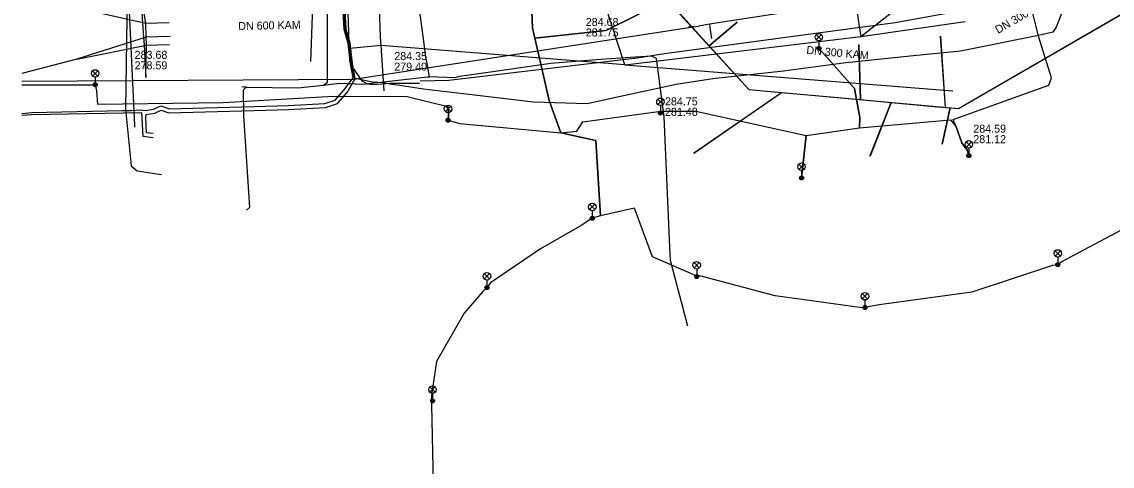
# Model space of a CAD drawing. Extents: x -599854 to -599675, y -1160809 to -1160543.
# Drawn here: x -599854.4 to -599745.4, y -1160665.1 to -1160620.8 of the extents above; entities that cross this region are included whole.
import ezdxf

# ---------------------------------------------------------------- set-up
doc = ezdxf.new("R2010")
doc.units = 0
for name, color, linetype in [('BKOM-ODVODNENI_trasa sítě', 7, 'Continuous'), ('BVK-JEDNOTNA_popisy', 7, 'Continuous'), ('BVK-VODOVOD_trasa sítě', 7, 'Continuous'), ('BVK-VODOVOD_trasa zrušené sítě', 7, 'Continuous'), ('CETIN_kabel podzemní', 7, 'Continuous'), ('DESTOVA-NEPROVOZOVANA_popisy', 7, 'Continuous'), ('DESTOVA_trasa neprovozované sítě', 7, 'Continuous'), ('DPMB_trolejové vedení-nosné lano', 7, 'Continuous'), ('DSP-JEDNOTNA-BVK_trasa sítě', 7, 'Continuous'), ('EON-NN_kabel', 7, 'Continuous'), ('EON-VN_kabel', 7, 'Continuous'), ('EON-VN_kabel zrušené sítě', 7, 'Continuous'), ('INNOGY-STL_trasa sítě', 7, 'Continuous'), ('TSB_kabel VO', 7, 'Continuous'), ('TSB_lampy VO', 7, 'Continuous')]:
    doc.layers.add(name, color=color, linetype=linetype)

msp = doc.modelspace()

# ---------------------------------------------------------------- linework, layer by layer
at = {"layer": 'BKOM-ODVODNENI_trasa sítě'}
for points in [[(-599760.76, -1160629.44), (-599734.15, -1160614)], [(-599790.33, -1160618.08), (-599781.73, -1160627.53)], [(-599782.89, -1160620.82), (-599785.679, -1160623.191)], [(-599762.55, -1160622.224), (-599762.081, -1160629.32)], [(-599770.714, -1160623.06), (-599770.546, -1160628.549)], [(-599787.215, -1160633.879), (-599778.44, -1160627.83)], [(-599781.73, -1160627.53), (-599760.76, -1160629.44)], [(-599769.597, -1160634.144), (-599767.509, -1160628.825)], [(-599762.401, -1160632.981), (-599761.583, -1160629.365)]]:
    msp.add_lwpolyline(points, dxfattribs=at)
at = {"layer": 'BVK-JEDNOTNA_popisy'}
for p, q in [((-599843.102, -1160624.605), (-599843.102, -1160624.605)), ((-599817.149, -1160624.73), (-599817.149, -1160624.73))]:
    msp.add_line(p, q, dxfattribs=at)
at = {"layer": 'BVK-VODOVOD_trasa sítě'}
msp.add_lwpolyline([(-599843.85, -1160617.9), (-599843.85, -1160618.1), (-599844.02, -1160629.49), (-599843.44, -1160635.17), (-599842.84, -1160635.66), (-599840.428, -1160636.038)], dxfattribs=at)
at = {"layer": 'BVK-VODOVOD_trasa zrušené sítě'}
for p, q in [((-599787.48, -1160621.25), (-599787.169, -1160621.208)), ((-599785.657, -1160621.012), (-599786.76, -1160621.23)), ((-599785.657, -1160621.012), (-599785.6, -1160621.34)), ((-599785.6, -1160621.34), (-599785.44, -1160622.44))]:
    msp.add_line(p, q, dxfattribs=at)
for points in [[(-599679.2237, -1160599.5579), (-599732.933, -1160612.912), (-599785.657, -1160621.012)], [(-599854.3744, -1160626.7017), (-599821.206, -1160626.503), (-599787.72, -1160621.365), (-599786.76, -1160621.23)], [(-599787.72, -1160621.365), (-599787.732, -1160621.288), (-599787.48, -1160621.25)]]:
    msp.add_lwpolyline(points, dxfattribs=at)
at = {"layer": 'CETIN_kabel podzemní'}
for points in [[(-599824.21, -1160627.1), (-599823.81, -1160626.82), (-599823.81, -1160615.51), (-599823.3, -1160614.12)], [(-599813.64, -1160626.29), (-599814.01, -1160624.26), (-599815.06, -1160616.21), (-599815.12, -1160614.04)], [(-599793.07, -1160624.32), (-599796.96, -1160624.59), (-599801.51, -1160624.95), (-599808.7, -1160625.98), (-599810.63, -1160626.23)], [(-599790.72, -1160626.2), (-599790.96, -1160624.46), (-599791.4, -1160624.2), (-599793.07, -1160624.32)], [(-599824.21, -1160627.1), (-599822.63, -1160626.91), (-599820.3, -1160627.01), (-599813.83, -1160626.28), (-599813.64, -1160626.29)], [(-599810.63, -1160626.23), (-599811.1, -1160626.39), (-599813.64, -1160626.29)], [(-599789.62, -1160643.27), (-599790.17, -1160630.26), (-599790.72, -1160626.2)], [(-599831.92, -1160627.32), (-599832.37, -1160627.29)], [(-599831.92, -1160627.32), (-599832.1, -1160627.43), (-599832.24, -1160627.61), (-599832.21, -1160630.13), (-599831.61, -1160639.31), (-599831.92, -1160639.58)], [(-599831.92, -1160627.32), (-599826.8, -1160627.36), (-599824.21, -1160627.1)], [(-599787.81, -1160651.17), (-599789.56, -1160644.6), (-599789.62, -1160643.27)]]:
    msp.add_lwpolyline(points, dxfattribs=at)
at = {"layer": 'DESTOVA-NEPROVOZOVANA_popisy'}
for p, q in [((-599798.016, -1160622.246), (-599798.016, -1160622.246)), ((-599790.097, -1160630.172), (-599790.097, -1160630.172)), ((-599759.285, -1160632.897), (-599759.285, -1160632.897))]:
    msp.add_line(p, q, dxfattribs=at)
at = {"layer": 'DESTOVA_trasa neprovozované sítě'}
for p, q in [((-599825.49, -1160624.76), (-599825.3, -1160619.266)), ((-599782.89, -1160620.82), (-599785.679, -1160623.191)), ((-599762.6, -1160622.21), (-599762.081, -1160629.32)), ((-599770.74, -1160623.07), (-599770.546, -1160628.549)), ((-599787.26, -1160633.89), (-599778.444, -1160627.829)), ((-599769.6, -1160634.18), (-599767.509, -1160628.825)), ((-599762.4, -1160633), (-599761.583, -1160629.365))]:
    msp.add_line(p, q, dxfattribs=at)
for points in [[(-599760.76, -1160629.44), (-599739.456, -1160617.079), (-599737.061, -1160615.689), (-599734.15, -1160614)], [(-599790.33, -1160618.08), (-599789.314, -1160619.197), (-599785.679, -1160623.191), (-599781.73, -1160627.53)], [(-599781.73, -1160627.53), (-599778.444, -1160627.829), (-599770.546, -1160628.549), (-599767.509, -1160628.825), (-599762.081, -1160629.32), (-599761.583, -1160629.365), (-599760.76, -1160629.44)]]:
    msp.add_lwpolyline(points, dxfattribs=at)
at = {"layer": 'DPMB_trolejové vedení-nosné lano'}
for points in [[(-599771.54, -1160615.69), (-599770.53, -1160622.26)], [(-599770.53, -1160622.26), (-599762.45, -1160615.93)], [(-599841.968, -1160626.344), (-599841.918, -1160623.101), (-599841.952, -1160622.311), (-599841.994, -1160620.91), (-599842.088, -1160620.363), (-599842.528, -1160616.745)], [(-599842.528, -1160616.745), (-599842.355, -1160620.405), (-599842.326, -1160620.901), (-599842.2, -1160622.364), (-599842.157, -1160623.068), (-599841.968, -1160626.344)], [(-599849.894, -1160619.17), (-599841.994, -1160620.91), (-599839.648, -1160620.839)], [(-599818.53, -1160622.33), (-599818.64, -1160619.44)], [(-599794.1, -1160625.09), (-599796.09, -1160619.09)], [(-599770.53, -1160622.26), (-599760.09, -1160620.75)], [(-599839.532, -1160622.265), (-599841.952, -1160622.311), (-599848.86, -1160624.505), (-599854.3744, -1160625.9564)], [(-599818.47, -1160623.14), (-599818.53, -1160622.33)], [(-599794.1, -1160625.09), (-599770.53, -1160622.26)], [(-599848.86, -1160624.505), (-599841.918, -1160623.101), (-599839.611, -1160623.045)], [(-599818.47, -1160623.14), (-599821.582, -1160623.44)], [(-599818.472, -1160623.141), (-599818.47, -1160623.14)], [(-599794.1, -1160625.09), (-599818.472, -1160623.141)], [(-599818.15, -1160627.66), (-599818.47, -1160623.14)], [(-599794.1, -1160625.09), (-599761.33, -1160627.66)]]:
    msp.add_lwpolyline(points, dxfattribs=at)
at = {"layer": 'DSP-JEDNOTNA-BVK_trasa sítě'}
for p, q in [((-599760.76, -1160629.44), (-599739.456, -1160617.079)), ((-599789.314, -1160619.197), (-599785.679, -1160623.191)), ((-599785.679, -1160623.191), (-599782.89, -1160620.82)), ((-599762.6, -1160622.21), (-599762.081, -1160629.32)), ((-599785.679, -1160623.191), (-599781.73, -1160627.53)), ((-599770.546, -1160628.549), (-599770.74, -1160623.07)), ((-599787.26, -1160633.89), (-599778.444, -1160627.829)), ((-599781.73, -1160627.53), (-599778.444, -1160627.829)), ((-599778.444, -1160627.829), (-599770.546, -1160628.549)), ((-599770.546, -1160628.549), (-599767.509, -1160628.825)), ((-599767.509, -1160628.825), (-599769.6, -1160634.18)), ((-599767.509, -1160628.825), (-599762.081, -1160629.32)), ((-599761.583, -1160629.365), (-599762.4, -1160633)), ((-599762.081, -1160629.32), (-599761.583, -1160629.365)), ((-599761.583, -1160629.365), (-599760.76, -1160629.44))]:
    msp.add_line(p, q, dxfattribs=at)
at = {"layer": 'EON-NN_kabel'}
for points in [[(-599844.347, -1160629.647), (-599843.403, -1160629.644), (-599842.517, -1160629.564), (-599842.022, -1160629.649), (-599841.199, -1160629.508), (-599840.468, -1160629.174), (-599839.62, -1160629.458), (-599836.082, -1160629.367), (-599831.164, -1160629.231), (-599827.751, -1160629.149), (-599824.103, -1160628.941), (-599823.051, -1160628.59), (-599822.19, -1160627.612), (-599821.256, -1160626.388), (-599821.529, -1160624.975), (-599821.758, -1160622.96), (-599822.159, -1160621.557), (-599822.4, -1160617.205)], [(-599841.262, -1160631.935), (-599841.918, -1160631.867), (-599841.979, -1160630.337), (-599841.955, -1160630.044), (-599841.082, -1160629.894), (-599840.447, -1160629.604), (-599839.683, -1160629.86), (-599836.059, -1160629.767), (-599831.139, -1160629.631), (-599827.719, -1160629.548), (-599824.028, -1160629.338), (-599822.822, -1160628.936), (-599821.85, -1160627.831), (-599821.044, -1160626.432), (-599821.331, -1160624.945), (-599821.562, -1160622.92), (-599821.961, -1160621.523), (-599822.2, -1160617.195)], [(-599854.3744, -1160629.9274), (-599853.387, -1160629.841), (-599844.347, -1160629.647)], [(-599854.3744, -1160630.0994), (-599853.359, -1160630.024), (-599842.397, -1160629.838), (-599842.295, -1160632.21), (-599841.252, -1160632.339)]]:
    msp.add_lwpolyline(points, dxfattribs=at)
at = {"layer": 'EON-VN_kabel'}
for points in [[(-599817.41, -1160627.04), (-599817.969, -1160626.93), (-599818.17, -1160626.89), (-599819.337, -1160626.809), (-599820.462, -1160626.561), (-599821.15, -1160626.41), (-599821.377, -1160625.236), (-599821.43, -1160624.96), (-599821.66, -1160622.94), (-599821.681, -1160622.866), (-599822.06, -1160621.54), (-599822.3, -1160617.2)], [(-599743.23, -1160617.28), (-599748.93, -1160618.14), (-599749.59, -1160618.4), (-599750.25, -1160619.35), (-599750.99, -1160621.33), (-599751.35, -1160621.82), (-599752.03, -1160621.98), (-599752.78, -1160622.16), (-599760.56, -1160623.7), (-599765.25, -1160624.19), (-599772.02, -1160624.87), (-599778.24, -1160625.7), (-599785.33, -1160626.46), (-599788.97, -1160627.03), (-599794.53, -1160628.24), (-599797.86, -1160628.96), (-599803.25, -1160628.81), (-599809.12, -1160628.1), (-599814.22, -1160627.49), (-599816.61, -1160627.15), (-599817.41, -1160627.04)]]:
    msp.add_lwpolyline(points, dxfattribs=at)
at = {"layer": 'EON-VN_kabel zrušené sítě'}
for points in [[(-599771.83, -1160621.47), (-599767.08, -1160620.85), (-599761.41, -1160619.81), (-599756.57, -1160618.89), (-599746.77, -1160617.22), (-599743.21, -1160616.58), (-599737.23, -1160615.44), (-599733.76, -1160614.74), (-599727.53, -1160613.39), (-599722.82, -1160612.38), (-599722.81, -1160612.35), (-599713.101, -1160609.819)], [(-599821.89, -1160616.75), (-599821.681, -1160622.866), (-599821.62, -1160624.66), (-599821.45, -1160625.13), (-599821.377, -1160625.236), (-599820.462, -1160626.561), (-599820.38, -1160626.68), (-599819.82, -1160626.98), (-599819.3, -1160627.05), (-599817.969, -1160626.93), (-599817.64, -1160626.9), (-599814.64, -1160626.92)], [(-599814.557, -1160626.669), (-599811.696, -1160626.619), (-599792.86, -1160624.37), (-599790.16, -1160623.96), (-599771.83, -1160621.47)]]:
    msp.add_lwpolyline(points, dxfattribs=at)
at = {"layer": 'INNOGY-STL_trasa sítě'}
msp.add_lwpolyline([(-599843.87, -1160614.73), (-599843.799, -1160616.23), (-599843.1, -1160631.11), (-599843.1, -1160631.3)], dxfattribs=at)
at = {"layer": 'TSB_kabel VO'}
for points in [[(-599800.51, -1160631.88), (-599801.66, -1160628.63), (-599803.35, -1160621.4), (-599803.6, -1160615.14), (-599817.16, -1160614.58), (-599825.47, -1160614.78), (-599827.84, -1160614.21), (-599835.21, -1160614.5), (-599849.27, -1160614.99), (-599854.3744, -1160615.0219)], [(-599803.6, -1160615.14), (-599803.35, -1160621.4), (-599803.12, -1160622.43), (-599796.01, -1160621.65), (-599790.01, -1160618.69)], [(-599790.01, -1160618.69), (-599796.01, -1160621.65), (-599803.12, -1160622.43), (-599801.66, -1160628.63), (-599800.51, -1160631.88)], [(-599800.51, -1160631.88), (-599798.91, -1160631.7), (-599798.3, -1160630.78), (-599790.741, -1160629.747), (-599790.55, -1160629.89), (-599790.384, -1160629.713), (-599787.03, -1160629.69), (-599776, -1160632.13), (-599776.45, -1160636.37), (-599776, -1160632.13), (-599770.65, -1160631.36), (-599770.62, -1160630.34), (-599771.15, -1160627.45), (-599774, -1160624.23), (-599774.72, -1160623.44), (-599774, -1160624.23), (-599771.15, -1160627.45), (-599770.62, -1160630.34), (-599770.65, -1160631.36), (-599761.55, -1160630.57), (-599761, -1160631.27), (-599760.44, -1160632.88), (-599759.91, -1160633.6), (-599759.73, -1160634.14), (-599759.91, -1160633.6), (-599760.44, -1160632.88), (-599761, -1160631.27), (-599761.31, -1160630.537), (-599751.73, -1160627.11), (-599751.48, -1160626.36), (-599752.78, -1160622.23), (-599753.62, -1160618.73)], [(-599854.3744, -1160627.079), (-599847.04, -1160627.06)], [(-599847.04, -1160627.06), (-599846.91, -1160627.67), (-599846.82, -1160629.01), (-599834.24, -1160628.85), (-599823.21, -1160628.2), (-599815.85, -1160628.24), (-599811.79, -1160629.23), (-599811.72, -1160630.1), (-599811.78, -1160630.6), (-599810.61, -1160630.92), (-599800.51, -1160631.88)], [(-599800.51, -1160631.88), (-599797.02, -1160632.62), (-599796.54, -1160640.16), (-599797.36, -1160640.39), (-599798.39, -1160641.07), (-599802.54, -1160643.45), (-599807.52, -1160646.85), (-599807.89, -1160647.31), (-599808.32, -1160647.73), (-599810.17, -1160649.85), (-599812.92, -1160654.69), (-599813.41, -1160657.83), (-599813.45, -1160658.54), (-599813.42, -1160659.01), (-599813.171, -1160671.571)], [(-599742.3, -1160640.42), (-599750.4, -1160644.71), (-599750.84, -1160645.03), (-599751.36, -1160645.11), (-599759.42, -1160647.76), (-599768.7, -1160649.02), (-599770.11, -1160649.3), (-599770.4, -1160649.33), (-599779.07, -1160648.14), (-599786.62, -1160646.13), (-599786.93, -1160646.21), (-599787.22, -1160646.03), (-599791.35, -1160644.25), (-599793.13, -1160639.37), (-599796.54, -1160640.16), (-599797.02, -1160632.62), (-599800.51, -1160631.88)]]:
    msp.add_lwpolyline(points, dxfattribs=at)
at = {"layer": 'TSB_lampy VO'}
for p, q in [((-599774.985, -1160622.58), (-599774.455, -1160622.05)), ((-599774.985, -1160622.05), (-599774.455, -1160622.58)), ((-599774.985, -1160622.58), (-599774.455, -1160622.05)), ((-599774.985, -1160622.05), (-599774.455, -1160622.58)), ((-599774.72, -1160622.69), (-599774.72, -1160623.44)), ((-599774.72, -1160622.69), (-599774.72, -1160623.44)), ((-599847.305, -1160626.2), (-599846.775, -1160625.67)), ((-599847.305, -1160625.67), (-599846.775, -1160626.2)), ((-599847.305, -1160626.2), (-599846.775, -1160625.67)), ((-599847.305, -1160625.67), (-599846.775, -1160626.2)), ((-599847.04, -1160626.31), (-599847.04, -1160627.06)), ((-599847.04, -1160626.31), (-599847.04, -1160627.06)), ((-599812.045, -1160629.74), (-599811.515, -1160629.21)), ((-599812.045, -1160629.21), (-599811.515, -1160629.74)), ((-599812.045, -1160629.74), (-599811.515, -1160629.21)), ((-599812.045, -1160629.21), (-599811.515, -1160629.74)), ((-599790.815, -1160629.03), (-599790.285, -1160628.5)), ((-599790.815, -1160628.5), (-599790.285, -1160629.03)), ((-599790.815, -1160629.03), (-599790.285, -1160628.5)), ((-599790.815, -1160628.5), (-599790.285, -1160629.03)), ((-599790.55, -1160629.14), (-599790.55, -1160629.89)), ((-599790.55, -1160629.14), (-599790.55, -1160629.89)), ((-599811.78, -1160629.85), (-599811.78, -1160630.6)), ((-599811.78, -1160629.85), (-599811.78, -1160630.6)), ((-599759.995, -1160633.28), (-599759.465, -1160632.75)), ((-599759.995, -1160632.75), (-599759.465, -1160633.28)), ((-599759.995, -1160633.28), (-599759.465, -1160632.75)), ((-599759.995, -1160632.75), (-599759.465, -1160633.28)), ((-599759.73, -1160633.39), (-599759.73, -1160634.14)), ((-599759.73, -1160633.39), (-599759.73, -1160634.14)), ((-599776.715, -1160635.51), (-599776.185, -1160634.98)), ((-599776.715, -1160634.98), (-599776.185, -1160635.51)), ((-599776.715, -1160635.51), (-599776.185, -1160634.98)), ((-599776.715, -1160634.98), (-599776.185, -1160635.51)), ((-599776.45, -1160635.62), (-599776.45, -1160636.37)), ((-599776.45, -1160635.62), (-599776.45, -1160636.37)), ((-599797.625, -1160639.53), (-599797.095, -1160639)), ((-599797.625, -1160639), (-599797.095, -1160639.53)), ((-599797.625, -1160639.53), (-599797.095, -1160639)), ((-599797.625, -1160639), (-599797.095, -1160639.53)), ((-599797.36, -1160639.64), (-599797.36, -1160640.39)), ((-599797.36, -1160639.64), (-599797.36, -1160640.39)), ((-599751.105, -1160644.17), (-599750.575, -1160643.64)), ((-599751.105, -1160643.64), (-599750.575, -1160644.17)), ((-599751.105, -1160644.17), (-599750.575, -1160643.64)), ((-599751.105, -1160643.64), (-599750.575, -1160644.17)), ((-599750.84, -1160644.28), (-599750.84, -1160645.03)), ((-599750.84, -1160644.28), (-599750.84, -1160645.03)), ((-599787.195, -1160645.35), (-599786.665, -1160644.82)), ((-599787.195, -1160644.82), (-599786.665, -1160645.35)), ((-599787.195, -1160645.35), (-599786.665, -1160644.82)), ((-599787.195, -1160644.82), (-599786.665, -1160645.35)), ((-599786.93, -1160645.46), (-599786.93, -1160646.21)), ((-599786.93, -1160645.46), (-599786.93, -1160646.21)), ((-599808.155, -1160646.45), (-599807.625, -1160645.92)), ((-599808.155, -1160645.92), (-599807.625, -1160646.45)), ((-599808.155, -1160646.45), (-599807.625, -1160645.92)), ((-599808.155, -1160645.92), (-599807.625, -1160646.45)), ((-599807.89, -1160646.56), (-599807.89, -1160647.31)), ((-599807.89, -1160646.56), (-599807.89, -1160647.31)), ((-599770.375, -1160648.44), (-599769.845, -1160647.91)), ((-599770.375, -1160647.91), (-599769.845, -1160648.44)), ((-599770.375, -1160648.44), (-599769.845, -1160647.91)), ((-599770.375, -1160647.91), (-599769.845, -1160648.44)), ((-599770.11, -1160648.55), (-599770.11, -1160649.3)), ((-599770.11, -1160648.55), (-599770.11, -1160649.3)), ((-599813.594, -1160657.76), (-599813.064, -1160657.23)), ((-599813.594, -1160657.23), (-599813.064, -1160657.76)), ((-599813.594, -1160657.76), (-599813.064, -1160657.23)), ((-599813.594, -1160657.23), (-599813.064, -1160657.76)), ((-599813.329, -1160657.87), (-599813.329, -1160658.62)), ((-599813.329, -1160657.87), (-599813.329, -1160658.62))]:
    msp.add_line(p, q, dxfattribs=at)
for centre, radius in [((-599774.72, -1160622.315), 0.375), ((-599774.72, -1160622.315), 0.375), ((-599774.72, -1160623.44), 0.2), ((-599774.72, -1160623.44), 0.2), ((-599774.72, -1160623.44), 0.1445), ((-599774.72, -1160623.44), 0.1445), ((-599774.72, -1160623.44), 0.0876), ((-599774.72, -1160623.44), 0.0876), ((-599847.04, -1160625.935), 0.375), ((-599847.04, -1160625.935), 0.375), ((-599847.04, -1160627.06), 0.2), ((-599847.04, -1160627.06), 0.2), ((-599847.04, -1160627.06), 0.1445), ((-599847.04, -1160627.06), 0.1445), ((-599847.04, -1160627.06), 0.0876), ((-599847.04, -1160627.06), 0.0876), ((-599790.55, -1160628.765), 0.375), ((-599790.55, -1160628.765), 0.375), ((-599811.78, -1160629.475), 0.375), ((-599811.78, -1160629.475), 0.375), ((-599811.78, -1160630.6), 0.2), ((-599811.78, -1160630.6), 0.2), ((-599811.78, -1160630.6), 0.1445), ((-599811.78, -1160630.6), 0.1445), ((-599811.78, -1160630.6), 0.0876), ((-599811.78, -1160630.6), 0.0876), ((-599790.55, -1160629.89), 0.2), ((-599790.55, -1160629.89), 0.2), ((-599790.55, -1160629.89), 0.1445), ((-599790.55, -1160629.89), 0.1445), ((-599790.55, -1160629.89), 0.0876), ((-599790.55, -1160629.89), 0.0876), ((-599759.73, -1160633.015), 0.375), ((-599759.73, -1160633.015), 0.375), ((-599776.45, -1160635.245), 0.375), ((-599776.45, -1160635.245), 0.375), ((-599759.73, -1160634.14), 0.2), ((-599759.73, -1160634.14), 0.2), ((-599759.73, -1160634.14), 0.1445), ((-599759.73, -1160634.14), 0.1445), ((-599759.73, -1160634.14), 0.0876), ((-599759.73, -1160634.14), 0.0876), ((-599776.45, -1160636.37), 0.2), ((-599776.45, -1160636.37), 0.2), ((-599776.45, -1160636.37), 0.1445), ((-599776.45, -1160636.37), 0.1445), ((-599776.45, -1160636.37), 0.0876), ((-599776.45, -1160636.37), 0.0876), ((-599797.36, -1160639.265), 0.375), ((-599797.36, -1160639.265), 0.375), ((-599797.36, -1160640.39), 0.2), ((-599797.36, -1160640.39), 0.2), ((-599797.36, -1160640.39), 0.1445), ((-599797.36, -1160640.39), 0.1445), ((-599797.36, -1160640.39), 0.0876), ((-599797.36, -1160640.39), 0.0876), ((-599750.84, -1160643.905), 0.375), ((-599750.84, -1160643.905), 0.375), ((-599786.93, -1160645.085), 0.375), ((-599786.93, -1160645.085), 0.375), ((-599807.89, -1160646.185), 0.375), ((-599807.89, -1160646.185), 0.375), ((-599750.84, -1160645.03), 0.2), ((-599750.84, -1160645.03), 0.2), ((-599750.84, -1160645.03), 0.1445), ((-599750.84, -1160645.03), 0.1445), ((-599750.84, -1160645.03), 0.0876), ((-599750.84, -1160645.03), 0.0876), ((-599786.93, -1160646.21), 0.2), ((-599786.93, -1160646.21), 0.2), ((-599786.93, -1160646.21), 0.1445), ((-599786.93, -1160646.21), 0.1445), ((-599786.93, -1160646.21), 0.0876), ((-599786.93, -1160646.21), 0.0876), ((-599807.89, -1160647.31), 0.2), ((-599807.89, -1160647.31), 0.2), ((-599807.89, -1160647.31), 0.1445), ((-599807.89, -1160647.31), 0.1445), ((-599807.89, -1160647.31), 0.0876), ((-599807.89, -1160647.31), 0.0876), ((-599770.11, -1160648.175), 0.375), ((-599770.11, -1160648.175), 0.375), ((-599770.11, -1160649.3), 0.2), ((-599770.11, -1160649.3), 0.2), ((-599770.11, -1160649.3), 0.1445), ((-599770.11, -1160649.3), 0.1445), ((-599770.11, -1160649.3), 0.0876), ((-599770.11, -1160649.3), 0.0876), ((-599813.329, -1160657.495), 0.375), ((-599813.329, -1160657.495), 0.375), ((-599813.329, -1160658.62), 0.2), ((-599813.329, -1160658.62), 0.2), ((-599813.329, -1160658.62), 0.1445), ((-599813.329, -1160658.62), 0.1445), ((-599813.329, -1160658.62), 0.0876), ((-599813.329, -1160658.62), 0.0876)]:
    msp.add_circle(centre, radius, dxfattribs=at)

# ---------------------------------------------------------------- texts
at = {"layer": 'BVK-JEDNOTNA_popisy'}
msp.add_text('DN 600 KAM', height=0.8, rotation=1.260508, dxfattribs=at).set_placement((-599832.736, -1160621.611))
for s, p in [('283.68', (-599843.102, -1160624.48)), ('284.35', (-599817.149, -1160624.605)), ('278.59', (-599843.102, -1160625.53)), ('279.40', (-599817.149, -1160625.655))]:
    msp.add_text(s, height=0.8, dxfattribs=at).set_placement(p)
at = {"layer": 'DESTOVA-NEPROVOZOVANA_popisy'}
for rotation, p in [(30.123719, (-599756.81, -1160621.998)), (354.795719, (-599775.99, -1160623.98))]:
    msp.add_text('DN 300 KAM', height=0.8, rotation=rotation, dxfattribs=at).set_placement(p)
for s, p in [('284.68', (-599798.016, -1160621.196)), ('281.75', (-599798.016, -1160622.246)), ('284.75', (-599790.097, -1160629.122)), ('281.48', (-599790.097, -1160630.172)), ('284.59', (-599759.285, -1160631.847)), ('281.12', (-599759.285, -1160632.897))]:
    msp.add_text(s, height=0.8, dxfattribs=at).set_placement(p)

doc.saveas('drawing.dxf')
